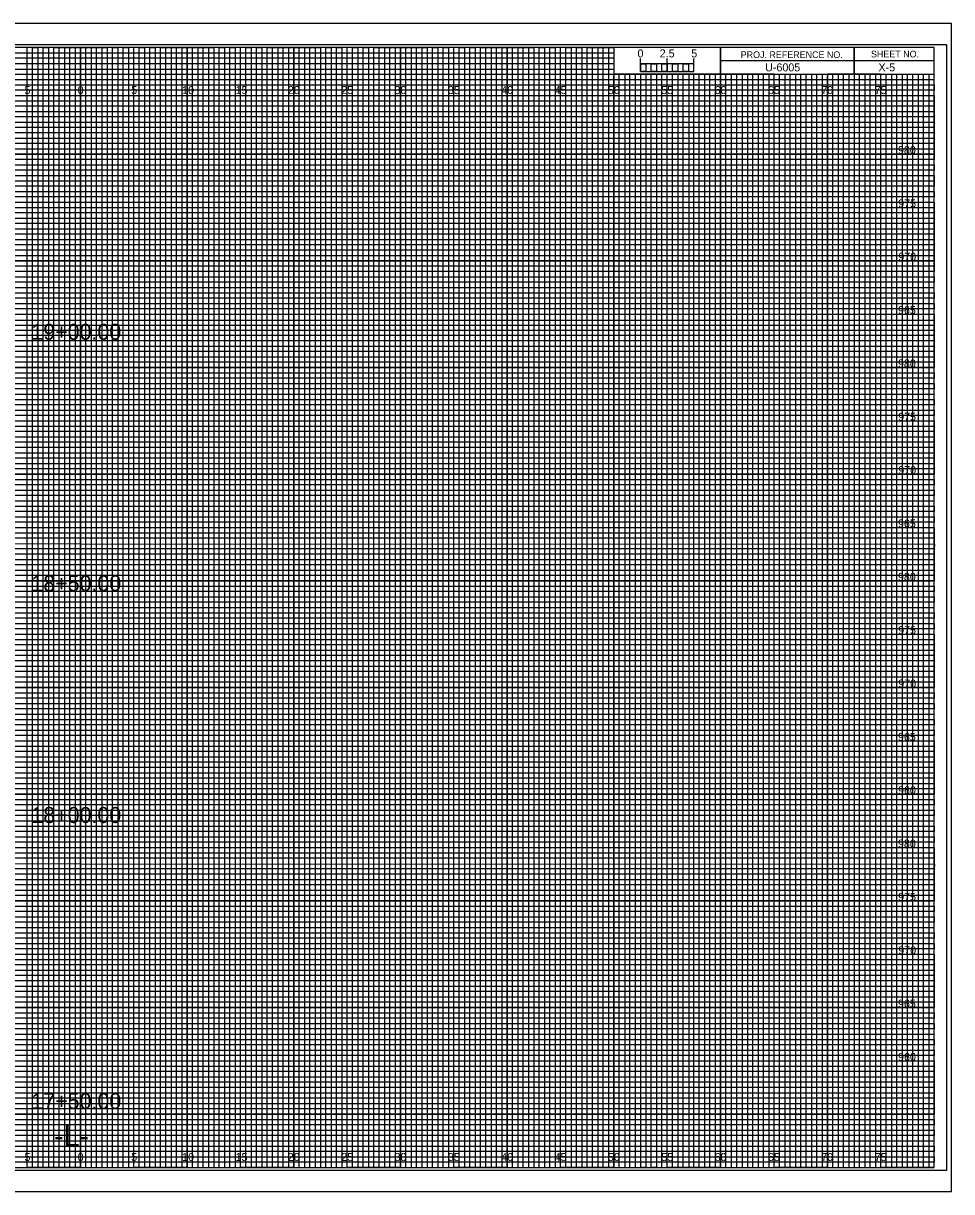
# Model space of a CAD drawing. Extents: x -7 to 162, y 328 to 437.
# Drawn here: x 74.6 to 161.7, y 327.7 to 437.2 of the extents above; entities that cross this region are included whole.
import ezdxf

# ---------------------------------------------------------------- set-up
doc = ezdxf.new("R2010")
doc.units = 0
for name, color, linetype in [('Prop XS Alignment Label', 7, 'Continuous'), ('Prop XS Bar Scale Labels', 7, 'Continuous'), ('Prop XS Elevation Labels', 7, 'Continuous'), ('Prop XS Offset Labels', 7, 'Continuous'), ('Prop XS Project Number', 7, 'Continuous'), ('Prop XS Sheet Number', 7, 'Continuous'), ('Prop XS Station Labels', 7, 'Continuous'), ('Sheet Cross Section CELL', 7, 'Continuous'), ('Sheet Cross Section Grid Major CELL', 7, 'Continuous'), ('Sheet Cross Section Grid Middle CELL', 7, 'Continuous'), ('Sheet Cross Section Grid Minor 1 CELL', 7, 'Continuous'), ('Sheet Cross Section Grid Minor 2 CELL', 7, 'Continuous'), ('Sheet Cross Section Scale CELL', 7, 'Continuous'), ('Sheet Cutting Line CELL', 7, 'Continuous'), ('Sheet DOT Grid CELL', 7, 'Continuous'), ('Sheet Plot Border Inside CELL', 7, 'Continuous'), ('Sheet Plot Border Outside CELL', 7, 'Continuous')]:
    doc.layers.add(name, color=color, linetype=linetype)

msp = doc.modelspace()

# ---------------------------------------------------------------- linework, layer by layer
at = {"layer": 'Sheet Cross Section CELL'}
for p, q in [((152.5, 435), (152.5, 432.5)), ((152.5, 432.5), (152.5, 435)), ((160, 433.75), (140, 433.75)), ((140, 433.75), (140, 432.5)), ((140, 432.5), (160, 432.5))]:
    msp.add_line(p, q, dxfattribs=at)
for points in [[(160, 435), (0, 435), (0, 330), (160, 330)], [(140, 435), (130, 435), (130, 432.51), (140, 432.51)], [(160, 435), (140, 435), (140, 432.5), (160, 432.5)]]:
    msp.add_lwpolyline(points, close=True, dxfattribs=at)
at = {"layer": 'Sheet Cross Section Grid Major CELL'}
for p, q in [((75, 435), (70, 435)), ((75, 330), (75, 435)), ((85, 435), (80, 435)), ((80, 435), (80, 330)), ((85, 330), (85, 435)), ((95, 435), (90, 435)), ((90, 435), (90, 330)), ((95, 330), (95, 435)), ((105, 435), (100, 435)), ((100, 435), (100, 330)), ((105, 330), (105, 435)), ((115, 435), (110, 435)), ((110, 435), (110, 330)), ((115, 330), (115, 435)), ((125, 435), (120, 435)), ((120, 435), (120, 330)), ((125, 330), (125, 435)), ((130, 435), (130, 330)), ((135, 330), (135, 432.5)), ((145, 432.5), (140, 432.5)), ((140, 432.5), (140, 330)), ((145, 330), (145, 432.5)), ((155, 432.5), (150, 432.5)), ((150, 432.5), (150, 330)), ((155, 330), (155, 432.5)), ((80, 330), (75, 330)), ((90, 330), (85, 330)), ((100, 330), (95, 330)), ((110, 330), (105, 330)), ((120, 330), (115, 330)), ((130, 330), (125, 330)), ((140, 330), (135, 330)), ((150, 330), (145, 330)), ((160, 330), (155, 330)), ((160, 330), (160, 330))]:
    msp.add_line(p, q, dxfattribs=at)
for points in [[(0, 430), (160, 430), (160, 425), (0, 425)], [(0, 420), (160, 420), (160, 415), (0, 415)], [(0, 410), (160, 410), (160, 405), (0, 405)], [(0, 400), (160, 400), (160, 395), (0, 395)], [(0, 390), (160, 390), (160, 385), (0, 385)], [(0, 380), (160, 380), (160, 375), (0, 375)], [(0, 370), (160, 370), (160, 365), (0, 365)], [(0, 360), (160, 360), (160, 355), (0, 355)], [(0, 350), (160, 350), (160, 345), (0, 345)], [(0, 340), (160, 340), (160, 335), (0, 335)]]:
    msp.add_lwpolyline(points, dxfattribs=at)
at = {"layer": 'Sheet Cross Section Grid Middle CELL'}
for points in [[(72.5, 330), (77.5, 330), (77.5, 435), (82.5, 435), (82.5, 330), (87.5, 330), (87.5, 435), (92.5, 435), (92.5, 330), (97.5, 330), (97.5, 435), (102.5, 435), (102.5, 330), (107.5, 330), (107.5, 435), (112.5, 435), (112.5, 330), (117.5, 330), (117.5, 435), (122.5, 435), (122.5, 330), (127.5, 330), (127.5, 435), (129.97, 435), (130, 435), (130, 432.5), (132.5, 432.5), (132.5, 330), (137.5, 330), (137.5, 432.5), (142.5, 432.5), (142.5, 330), (147.5, 330), (147.5, 432.5), (152.5, 432.5), (152.5, 330), (157.5, 330), (157.5, 432.5)], [(0, 432.5), (137.5, 432.5)], [(0, 422.5), (160, 422.5), (160, 427.5), (0, 427.5)], [(0, 412.5), (160, 412.5), (160, 417.5), (0, 417.5)], [(0, 402.5), (160, 402.5), (160, 407.5), (0, 407.5)], [(0, 392.5), (160, 392.5), (160, 397.5), (0, 397.5)], [(0, 382.5), (160, 382.5), (160, 387.5), (0, 387.5)], [(0, 372.5), (160, 372.5), (160, 377.5), (0, 377.5)], [(0, 362.5), (160, 362.5), (160, 367.5), (0, 367.5)], [(0, 352.5), (160, 352.5), (160, 357.5), (0, 357.5)], [(0, 342.5), (160, 342.5), (160, 347.5), (0, 347.5)], [(0, 332.5), (160, 332.5), (160, 337.5), (0, 337.5)]]:
    msp.add_lwpolyline(points, dxfattribs=at)
at = {"layer": 'Sheet Cross Section Grid Minor 1 CELL'}
for p, q in [((0, 434.5), (130, 434.5)), ((130, 433.99), (0, 433.99)), ((130, 434.5), (130, 433.99)), ((0, 433.5), (130, 433.5)), ((130, 432.94), (0, 432.94)), ((130, 433.5), (130, 432.94)), ((0, 432), (160, 432))]:
    msp.add_line(p, q, dxfattribs=at)
for points in [[(0, 431.5), (135, 431.5), (160, 431.5), (160, 431), (0, 431)], [(0, 430.5), (160, 430.5), (160, 429.5), (0, 429.5)], [(0, 429), (160, 429), (160, 428.5), (0, 428.49)], [(0, 428), (160, 428), (160, 427), (0, 427)], [(0, 426.5), (160, 426.5), (160, 426), (0, 426)], [(0, 425.5), (160, 425.5), (160, 424.5), (0, 424.5)], [(0, 424), (160, 424), (160, 423.5), (0, 423.5)], [(0, 423), (160, 423), (160, 422), (0, 422)], [(0, 421.5), (160, 421.5), (160, 421), (0, 421)], [(0, 420.5), (160, 420.5), (160, 419.5), (0, 419.5)], [(0, 419), (160, 419), (160, 418.5), (0, 418.5)], [(0, 418), (160, 418), (160, 416.98), (160, 416.5), (160, 416), (0, 416)], [(0, 417), (160, 417), (160, 416.5), (0, 416.5)], [(0, 415.5), (160, 415.5), (160, 414.5), (0, 414.51)], [(0, 414.51), (160, 414.5), (160, 414), (0, 414)], [(0, 413.5), (160, 413.5), (160, 413), (0, 413)], [(0, 412), (160, 412), (160, 411.5), (0, 411.5)], [(0, 411), (160, 411), (160, 410.5), (0, 410.5)], [(-0.04, 409.44), (160, 409.44), (160, 408.94), (-0.04, 408.94)], [(0, 408.5), (160, 408.5), (160, 408), (0, 408)], [(0, 407), (160, 407), (160, 406.5), (0, 406.5)], [(0, 406), (160, 406), (160, 405.5), (0, 405.5)], [(0, 404.5), (160, 404.5), (160, 404), (0, 404)], [(0, 403.5), (160, 403.5), (160, 403), (0, 403)], [(0, 402), (160, 402), (160, 401.5), (0, 401.5)], [(0, 401), (160, 401), (160, 400.5), (0, 400.5)], [(0, 399.5), (160, 399.5), (160, 398.99), (0, 399)], [(0, 398.5), (160, 398.5), (160, 398), (0, 398)], [(0, 397), (160, 397), (160, 396.5), (0, 396.5)], [(0, 396), (160, 396), (160, 395.5), (0, 395.5)], [(0, 394.5), (160, 394.5), (160, 394), (0, 394)], [(0, 393.5), (160, 393.5), (160, 393), (0, 393)], [(0, 392), (160, 392), (160, 391.5), (0, 391.5)], [(0, 391), (160, 391), (160, 390.5), (0, 390.5)], [(0, 389.5), (160, 389.5), (160, 389), (0, 389)], [(0, 388.5), (160.03, 388.45), (160, 388), (0, 388)], [(0, 387), (160, 387), (160, 386.5), (0, 386.5)], [(0, 386), (160, 386), (160, 385.5), (0, 385.5)], [(0, 384.5), (160, 384.5), (160, 384), (0, 384)], [(0, 383.5), (160, 383.5), (160, 383), (0, 383)], [(0, 382), (160, 382), (160, 381.5), (0, 381.5)], [(0, 381), (160, 381), (160, 380.5), (0, 380.5)], [(0, 379.5), (160, 379.5), (160, 379), (0, 379)], [(0, 378.5), (160, 378.5), (160, 378), (0, 378)], [(0, 377), (160, 377), (160, 376.5), (0, 376.5)], [(0, 376), (160, 376), (160, 375.5), (0, 375.5)], [(0, 374.5), (160, 374.5), (160, 374), (0, 374)], [(0, 373.5), (160, 373.5), (160, 373), (0, 373)], [(0, 372), (160, 372), (160, 371.5), (0, 371.5)], [(0, 371), (160, 371), (160, 370.5), (0, 370.5)], [(0, 369.5), (160, 369.5), (160, 368.99), (0, 369)], [(0, 368.5), (160, 368.5), (160, 368), (0, 368)], [(0, 367), (160, 367), (160, 366.5), (0, 366.5)], [(0, 366), (160, 366), (160, 365.5), (0, 365.5)], [(0, 364.5), (160, 364.5), (160, 364), (0, 364)], [(0, 363.5), (160, 363.5), (160, 363), (0, 363)], [(0, 362), (160, 362), (160, 361.5), (0, 361.5)], [(0, 361), (160, 361), (160, 360.5), (0, 360.5)], [(0, 359.5), (160, 359.5), (160, 359), (0, 359)], [(0, 358.5), (160.03, 358.45), (160, 358), (0, 358)], [(0, 357), (160, 357), (160, 356.5), (0, 356.5)], [(0, 356), (160, 356), (160, 355.5), (0, 355.5)], [(0, 354.5), (160, 354.5), (160, 354), (0, 354)], [(0, 353.5), (160, 353.5), (160, 353), (0, 353)], [(0, 352), (160, 352), (160, 351.5), (0, 351.5)], [(0, 351), (160, 351), (160, 350.5), (0, 350.5)], [(0, 349.5), (160, 349.5), (160, 349), (0, 349)], [(0, 348.5), (160, 348.5), (160, 348), (0, 348)], [(0, 347), (160, 347), (160, 346.5), (0, 346.5)], [(0, 346), (160, 346), (160, 345.5), (0, 345.5)], [(0, 344.5), (160, 344.5), (160, 344), (0, 344)], [(0, 343.5), (160, 343.5), (160, 343), (0, 343)], [(0, 342), (160, 342), (160, 341.5), (0, 341.5)], [(0, 341), (160, 341), (160, 340.5), (0, 340.5)], [(0, 339.5), (160, 339.5), (160, 339), (0, 339)], [(0, 338.5), (160, 338.5), (160, 338), (0, 338)], [(0, 337), (160, 337), (160, 336.5), (0, 336.5)], [(0, 336), (160, 336), (160, 335.5), (0, 335.5)], [(0, 334.5), (160, 334.5), (160, 334), (0, 334)], [(0, 333.5), (160, 333.5), (160, 333), (0, 333)], [(0, 332), (160, 332), (160, 331.5), (0, 331.5)], [(0, 331), (160, 331), (160, 330.5), (0, 330.5)]]:
    msp.add_lwpolyline(points, dxfattribs=at)
at = {"layer": 'Sheet Cross Section Grid Minor 2 CELL'}
for p, q in [((133.5, 432.5), (133, 432.5)), ((133, 432.5), (133, 330)), ((133.5, 330), (133.5, 432.5)), ((134.5, 432.5), (134, 432.5)), ((134, 432.5), (134, 330)), ((134.5, 330), (134.5, 432.5)), ((133, 330), (132.5, 330)), ((134, 330), (133.5, 330))]:
    msp.add_line(p, q, dxfattribs=at)
for points in [[(75, 330), (75.5, 330), (75.5, 435), (76, 435), (76, 330)], [(76, 330), (76.5, 330), (76.5, 435), (77, 435), (77, 330)], [(77.5, 330), (78, 330), (78, 435), (78.5, 435), (78.5, 330)], [(78.5, 330), (79, 330), (79, 435), (79.5, 435), (79.5, 330)], [(80, 330), (80.5, 330), (80.5, 435), (81, 435), (81, 330)], [(81, 330), (81.5, 330), (81.5, 435), (82, 435), (82, 330)], [(82.5, 330), (83, 330), (83, 435), (83.5, 435), (83.5, 330)], [(83.5, 330), (84, 330), (84, 435), (84.5, 435), (84.5, 330)], [(85, 330), (85.5, 330), (85.5, 435), (86, 435), (86, 330)], [(86, 330), (86.5, 330), (86.5, 435), (87, 435), (87, 330)], [(87.5, 330), (88, 330), (88, 435), (88.5, 435), (88.5, 330)], [(88.5, 330), (89, 330), (89, 435), (89.5, 435), (89.5, 330)], [(90, 330), (90.5, 330), (90.5, 435), (91, 435), (91, 330)], [(91, 330), (91.5, 330), (91.5, 435), (92, 435), (92, 330)], [(92.5, 330), (93, 330), (93, 435), (93.5, 435), (93.5, 330)], [(93.5, 330), (94, 330), (94, 435), (94.5, 435), (94.5, 330)], [(95, 330), (95.5, 330), (95.5, 435), (96, 435), (96, 330)], [(96, 330), (96.5, 330), (96.5, 435), (97, 435), (97, 330)], [(97.5, 330), (98, 330), (98, 435), (98.5, 435), (98.5, 330)], [(98.5, 330), (99, 330), (99, 435), (99.5, 435), (99.5, 330)], [(100, 330), (100.5, 330), (100.5, 435), (101, 435), (101, 330)], [(101, 330), (101.5, 330), (101.5, 435), (102, 435), (102, 330)], [(102.5, 330), (103, 330), (103, 435), (103.5, 435), (103.5, 330)], [(103.5, 330), (104, 330), (104, 435), (104.5, 435), (104.5, 330)], [(105, 330), (105.5, 330), (105.5, 435), (106, 435), (106, 330)], [(106, 330), (106.5, 330), (106.5, 435), (107, 435), (107, 330)], [(107.5, 330), (108, 330), (108, 435), (108.5, 435), (108.5, 330)], [(108.5, 330), (109, 330), (109, 435), (109.5, 435), (109.5, 330)], [(110, 330), (110.5, 330), (110.5, 435), (111, 435), (111, 330)], [(111, 330), (111.5, 330), (111.5, 435), (112, 435), (112, 330)], [(112.5, 330), (113, 330), (113, 435), (113.5, 435), (113.5, 330)], [(113.5, 330), (114, 330), (114, 435), (114.5, 435), (114.5, 330)], [(115, 330), (115.5, 330), (115.5, 435), (116, 435), (116, 330)], [(116, 330), (116.5, 330), (116.5, 435), (117, 435), (117, 330)], [(117.5, 330), (118, 330), (118, 435), (118.5, 435), (118.5, 330)], [(118.5, 330), (119, 330), (119, 435), (119.5, 435), (119.5, 330)], [(120, 330), (120.5, 330), (120.5, 435), (121, 435), (121, 330)], [(121, 330), (121.5, 330), (121.5, 435), (122, 435), (122, 330)], [(122.5, 330), (123, 330), (123, 435), (123.5, 435), (123.5, 330)], [(123.5, 330), (124, 330), (124, 435), (124.5, 435), (124.5, 330)], [(125, 330), (125.5, 330), (125.5, 435), (126, 435), (126, 330)], [(126, 330), (126.5, 330), (126.5, 435), (127, 435), (127, 330)], [(127.5, 330), (128, 330), (128, 435), (128.5, 435), (128.5, 330)], [(128.5, 330), (129, 330), (129, 435), (129.5, 435), (129.5, 330)], [(130, 330), (130.5, 330), (130.5, 432.5), (131.01, 432.5), (131.01, 330)], [(131, 330), (131.5, 330), (131.5, 432.5), (132, 432.5), (132, 330)], [(135, 330), (135.49, 330), (135.49, 432.5), (136, 432.5), (136, 330)], [(136, 330), (136.5, 330), (136.5, 432.5), (137.03, 432.5), (137.03, 330)], [(137.5, 330), (138, 330), (138, 432.5), (138.5, 432.5), (138.5, 330)], [(138.5, 330), (139, 330), (139, 432.5), (139.5, 432.5), (139.5, 330)], [(140, 330), (140.5, 330), (140.5, 432.5), (141, 432.5), (141, 330)], [(141, 330), (141.5, 330), (141.5, 432.5), (142, 432.5), (142, 330)], [(142.5, 330), (143, 330), (143, 432.5), (143.5, 432.5), (143.5, 330)], [(143.5, 330), (144, 330), (144, 432.5), (144.5, 432.5), (144.5, 330)], [(145, 330), (145.5, 330), (145.5, 432.5), (146, 432.5), (146, 330)], [(146, 330), (146.5, 330), (146.5, 432.5), (147, 432.5), (147, 330)], [(147.5, 330), (148, 330), (148, 432.5), (148.5, 432.5), (148.5, 330)], [(148.5, 330), (149, 330), (149, 432.5), (149.5, 432.5), (149.5, 330)], [(150, 330), (150.5, 330), (150.5, 432.5), (151, 432.5), (151, 330)], [(151, 330), (151.5, 330), (151.5, 432.5), (152, 432.5), (152, 330)], [(152.5, 330), (153, 330), (153, 432.5), (153.5, 432.5), (153.5, 330)], [(153.5, 330), (154, 330), (154, 432.5), (154.5, 432.5), (154.5, 330)], [(155, 330), (155.5, 330), (155.5, 432.5), (156, 432.5), (156, 330)], [(156, 330), (156.5, 330), (156.5, 432.5), (157, 432.5), (157, 330)], [(157.5, 330), (158, 330), (158, 432.5), (158.5, 432.5), (158.5, 330)], [(158.5, 330), (159, 330), (159, 432.5), (159.5, 432.5), (159.5, 330)]]:
    msp.add_lwpolyline(points, dxfattribs=at)
at = {"layer": 'Sheet Cross Section Scale CELL'}
for p, q in [((132.5, 432.75), (132.5, 433.95)), ((132.5, 433.45), (132.5, 433.95)), ((135, 432.75), (135, 433.95)), ((137.5, 432.75), (137.5, 433.95)), ((137.5, 433.45), (137.5, 433.95))]:
    msp.add_line(p, q, dxfattribs=at)
for points in [[(137.5, 433.45), (132.5, 433.45), (132.5, 432.75), (137.5, 432.75)], [(132.5, 433.45), (133, 433.45), (133, 432.75), (132.5, 432.75)], [(133.5, 433.45), (134, 433.45), (134, 432.75), (133.5, 432.75)], [(134.5, 433.45), (135, 433.45), (135, 432.75), (134.5, 432.75)], [(135.5, 433.45), (136, 433.45), (136, 432.75), (135.5, 432.75)], [(136.5, 433.45), (137, 433.45), (137, 432.75), (136.5, 432.75)]]:
    msp.add_lwpolyline(points, close=True, dxfattribs=at)
at = {"layer": 'Sheet Cutting Line CELL'}
for p, q in [((161.65, 437.25), (-6.7, 437.25)), ((-6.7, 327.75), (161.65, 327.75))]:
    msp.add_line(p, q, dxfattribs=at)
at = {"layer": 'Sheet DOT Grid CELL'}
for p, q in [((75, 330), (75, 435)), ((80, 330), (80, 435)), ((85, 330), (85, 435)), ((90, 330), (90, 435)), ((95, 330), (95, 435)), ((100, 330), (100, 435)), ((105, 330), (105, 435)), ((110, 330), (110, 435)), ((115, 330), (115, 435)), ((120, 330), (120, 435)), ((125, 330), (125, 435)), ((130, 330), (130, 432.34)), ((135, 330), (135, 432.34)), ((140, 330), (140, 432.34)), ((145, 330), (145, 432.34)), ((150, 330), (150, 432.34)), ((155, 330), (155, 432.34)), ((0, 430), (160, 430)), ((0, 425), (160, 425)), ((0, 420), (160, 420)), ((0, 415), (160, 415)), ((0, 410), (160, 410)), ((0, 405), (160, 405)), ((0, 400), (160, 400)), ((0, 395), (160, 395)), ((0, 390), (160, 390)), ((0, 385), (160, 385)), ((0, 380), (160, 380)), ((0, 375), (160, 375)), ((0, 370), (160, 370)), ((0, 365), (160, 365)), ((0, 360), (160, 360)), ((0, 355), (160, 355)), ((0, 350), (160, 350)), ((0, 345), (160, 345)), ((0, 340), (160, 340)), ((0, 335), (160, 335))]:
    msp.add_line(p, q, dxfattribs=at)
at = {"layer": 'Sheet Plot Border Inside CELL'}
msp.add_lwpolyline([(-5.4, 329.75), (161.2, 329.75), (161.2, 435.25), (-5.4, 435.25)], close=True, dxfattribs=at)
at = {"layer": 'Sheet Plot Border Outside CELL'}
msp.add_lwpolyline([(-6.7, 327.75), (161.65, 327.75), (161.65, 437.25), (-6.7, 437.25)], close=True, dxfattribs=at)

# ---------------------------------------------------------------- texts
at = {"layer": 'Prop XS Alignment Label'}
msp.add_text('-L-', height=2, dxfattribs=at).set_placement((77.53, 332))
at = {"layer": 'Prop XS Bar Scale Labels'}
for s, p in [('2.5', (134.29, 434.06)), ('5', (137.24, 434.06))]:
    msp.add_text(s, height=0.75, dxfattribs=at).set_placement(p)
at = {"layer": 'Prop XS Elevation Labels'}
for s, p in [('980', (156.62, 425)), ('975', (156.64, 420)), ('970', (156.65, 415)), ('965', (156.62, 410)), ('980', (156.62, 405)), ('975', (156.64, 400)), ('970', (156.65, 395)), ('965', (156.62, 390)), ('980', (156.62, 385)), ('975', (156.64, 380)), ('970', (156.65, 375)), ('965', (156.62, 370)), ('960', (156.63, 365)), ('980', (156.62, 360)), ('975', (156.64, 355)), ('970', (156.65, 350)), ('965', (156.62, 345)), ('960', (156.63, 340))]:
    msp.add_text(s, height=0.75, dxfattribs=at).set_placement(p)
at = {"layer": 'Prop XS Offset Labels'}
for s, p in [('5', (74.74, 430.62)), ('0', (79.73, 430.62)), ('0', (79.73, 430.62)), ('5', (84.74, 430.62)), ('10', (89.52, 430.62)), ('15', (94.53, 430.62)), ('20', (99.43, 430.62)), ('25', (104.44, 430.62)), ('30', (109.43, 430.62)), ('35', (114.44, 430.62)), ('40', (119.43, 430.62)), ('45', (124.44, 430.62)), ('50', (129.43, 430.62)), ('55', (134.44, 430.62)), ('60', (139.43, 430.62)), ('65', (144.44, 430.62)), ('70', (149.43, 430.62)), ('75', (154.44, 430.62)), ('5', (74.74, 330.62)), ('0', (79.73, 330.62)), ('0', (79.73, 330.62)), ('5', (84.74, 330.62)), ('10', (89.52, 330.62)), ('15', (94.53, 330.62)), ('20', (99.43, 330.62)), ('25', (104.44, 330.62)), ('30', (109.43, 330.62)), ('35', (114.44, 330.62)), ('40', (119.43, 330.62)), ('45', (124.44, 330.62)), ('50', (129.43, 330.62)), ('55', (134.44, 330.62)), ('60', (139.43, 330.62)), ('65', (144.44, 330.62)), ('70', (149.43, 330.62)), ('75', (154.44, 330.62))]:
    msp.add_text(s, height=0.75, dxfattribs=at).set_placement(p)
at = {"layer": 'Prop XS Project Number'}
msp.add_text('U-6005', height=0.75, dxfattribs=at).set_placement((144.17, 432.75))
at = {"layer": 'Prop XS Sheet Number'}
msp.add_text('X-5', height=0.75, dxfattribs=at).set_placement((154.79, 432.75))
at = {"layer": 'Prop XS Station Labels'}
for s, p in [('19+00.00', (75.39, 407.59)), ('18+50.00', (75.39, 384.02)), ('18+00.00', (75.39, 362.3)), ('17+50.00', (75.39, 335.49))]:
    msp.add_text(s, height=1.5, dxfattribs=at).set_placement(p)
at = {"layer": 'Sheet Cross Section CELL'}
for s, p in [('PROJ. REFERENCE NO.', (141.88, 434)), ('SHEET NO.', (154.09, 434.06))]:
    msp.add_text(s, height=0.625, dxfattribs=at).set_placement(p)
at = {"layer": 'Sheet Cross Section Scale CELL'}
msp.add_text('0', height=0.75, dxfattribs=at).set_placement((132.21, 434.06))

doc.saveas('drawing.dxf')
